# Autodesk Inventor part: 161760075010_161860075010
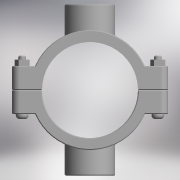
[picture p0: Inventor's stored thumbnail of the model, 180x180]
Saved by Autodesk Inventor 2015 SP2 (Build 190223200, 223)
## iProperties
Created: 2017-05
Part Number: 161760075010_161860075010
Material: Generic
Description: PLASSON DOUBLE SADDLE 75-1"
Document SubType Name: Modeling
Designer: KIM
Density: 1 g/cm^3
Appearance: Default
Author: KIM
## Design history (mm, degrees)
derived "16176.ipt"
feature "Solid1::16176.ipt"
feature "Solid2::16176.ipt"
tag "TaggingFeature1"
body "Solid1"
body "Solid2"
other parameters: "d0" = 93.75, "d1" = 122, "d2" = 37.5, "d3" = 75, "d4" = 98, "d5" = 0, "d6" = 6.1, "d7" = 122, "d8" = 0.1, "d10" = 0, "d11" = 0.75, "d20" = 0.75, "d23" = 0.75, "d37" = 8, "d38" = 45.5, "d39" = 0, "d40" = 3, "d41" = 5, "d42" = 0, "d43" = 6, "d44" = 3, "d45" = 0, "d46" = 0.75, "d52" = 30.291, "d53" = 21, "d54" = 0, "d55" = 25, "d57" = 0, "d58" = 81, "d60" = 0, "d63" = 8, "d66" = 82, "d67" = 134, "d68" = 39.3783, "d69" = 30.291, "d70" = 21, "d71" = 0, "d72" = 25, "d74" = 0, "d75" = 0.75, "d_" = 75, "B_" = 25, "G_" = 30.291, "A_" = 67, "L_" = 122, "L_1" = 98, "l_2" = 21
